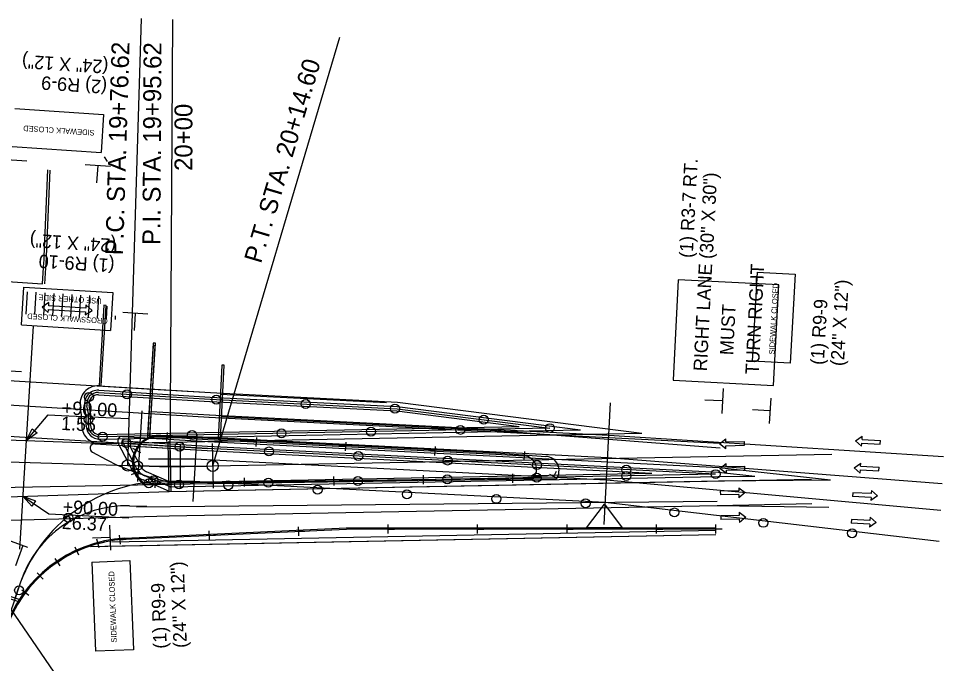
# Model space of a CAD drawing. Extents: x 659657 to 668193, y 633084 to 648639.
# Drawn here: x 662767.5 to 663181.2, y 642314.3 to 642602.8 of the extents above; entities that cross this region are included whole.
import ezdxf

# ---------------------------------------------------------------- set-up
doc = ezdxf.new("R2010")
doc.units = 0
for name, color, linetype in [('R_Border PE', 7, 'Continuous'), ('R_Draft', 7, 'Continuous'), ('R_MOT_Stage 1C_Striping', 7, 'Continuous'), ('R_MOT_Stage 2', 7, 'Continuous'), ('R_MOT_Stage 2_Striping', 7, 'Continuous'), ('R_MOT_Stage 3', 7, 'Continuous'), ('R_MOT_Stage 3_Striping', 7, 'Continuous'), ('R_MOT_Stage 4', 7, 'Continuous'), ('R_MOT_STAGE 4_ALG', 7, 'Continuous'), ('R_MOT_Stage 4_Striping', 7, 'Continuous'), ('R_MOT_Stage 5', 7, 'Continuous'), ('R_MOT_Stage 5_Striping', 7, 'Continuous'), ('R_MOT_Stage 5_Striping_PPM', 7, 'Continuous'), ('R_ROW Annot', 7, 'Continuous'), ('STRIPE-WHITE 12in', 7, 'Continuous'), ('T_Notes', 7, 'Continuous'), ('T_SIGNAL CONTROL CABINET', 7, 'Continuous'), ('TEXT_TEMP_SIGNAL_POLES_STAGE 2', 7, 'Continuous')]:
    doc.layers.add(name, color=color, linetype=linetype)

msp = doc.modelspace()

# ---------------------------------------------------------------- linework, layer by layer
for p, q in [((662739.64, 642446.41), (662768.94, 642444.98)), ((662786.79, 642425.28), (662816.56, 642423.84)), ((662713.96, 642406.03), (662816.41, 642402.89)), ((662787.14, 642380.99), (662816.91, 642379.54))]:
    msp.add_line(p, q)
for points in [[(662770.98, 642413.89), (662780.8, 642425.58), (662786.79, 642425.28)], [(662769.48, 642389.1), (662781.14, 642381.28), (662787.14, 642380.99)]]:
    msp.add_lwpolyline(points)
for points in [[(662770.98, 642413.89), (662773.61, 642419.28), (662775.84, 642417.41)], [(662769.48, 642389.1), (662775.13, 642387.07), (662773.51, 642384.65)]]:
    msp.add_lwpolyline(points, close=True)
msp.add_arc((662839.74, 643164.53), 762, 268.24549, 271.10143)
at = {"layer": 'R_Border PE'}
for p, q in [((662808.29, 642376.24), (662808.71, 642365)), ((662808.34, 642370.64), (662800.66, 642370.35)), ((662800.41, 642359.68), (662817.4, 642360.32)), ((662800.41, 642359.68), (662801.91, 642319.85)), ((662817.4, 642360.32), (662818.9, 642320.49)), ((662818.9, 642320.49), (662801.91, 642319.85))]:
    msp.add_line(p, q, dxfattribs=at)
at = {"layer": 'R_Draft'}
for p, q in [((662768.85, 642465.72), (662769.91, 642482.69)), ((662769.91, 642482.69), (662809.7, 642480.2)), ((662809.7, 642480.2), (662808.63, 642463.23)), ((662814.16, 642471.4), (662825.38, 642470.7)), ((662819.73, 642470.89), (662819.25, 642463.23)), ((662768.85, 642465.72), (662808.63, 642463.23))]:
    msp.add_line(p, q, dxfattribs=at)
for points in [[(662800.45, 642472.26), (662797.67, 642474.69), (662797.59, 642473.29), (662781.07, 642474.32), (662781.15, 642475.72), (662778.1, 642473.66), (662780.87, 642471.23), (662780.96, 642472.64), (662797.48, 642471.6), (662797.39, 642470.2)], [(663029.53, 642385.61), (663037.49, 642375), (663021.58, 642375)]]:
    msp.add_lwpolyline(points, close=True, dxfattribs=at)
at = {"layer": 'R_MOT_Stage 1C_Striping'}
for p, q in [((662817.25, 642384.85), (662824.86, 642384.64)), ((662768.45, 642350.7), (662761.02, 642328.43))]:
    msp.add_line(p, q, dxfattribs=at)
msp.add_arc((662815.88, 642334.87), 50, 88.4238, 161.5452, dxfattribs=at)
at = {"layer": 'R_MOT_Stage 2'}
for centre in [(662825.82, 642394.87), (662861.33, 642394.05), (662901.28, 642392.02), (662941.23, 642389.99), (662981.18, 642387.96), (663021.12, 642385.93), (663060.84, 642381.87), (662789.8, 642379.51), (663100.57, 642377.22), (663140.3, 642372.58), (662767.83, 642347.07)]:
    msp.add_circle(centre, 2, dxfattribs=at)
at = {"layer": 'R_MOT_Stage 2_Striping'}
for p, q in [((662826.92, 642427.09), (662852.91, 642425.52)), ((662852.76, 642425.52), (663031.46, 642416.45)), ((662826.23, 642415.85), (662847.24, 642415.84)), ((662847.24, 642415.84), (662852.3, 642415.53)), ((662852.3, 642415.53), (663030.95, 642406.46)), ((663031.46, 642416.45), (663181.16, 642406.84)), ((662825.61, 642405.87), (662846.63, 642405.86)), ((662846.63, 642405.86), (662851.7, 642405.55)), ((662851.7, 642405.55), (663030.44, 642396.47)), ((663030.95, 642406.46), (663180.55, 642394.85)), ((663030.44, 642396.47), (663179.94, 642382.87)), ((662833.88, 642395.88), (662846.03, 642395.9)), ((662846.03, 642395.9), (662851.1, 642395.57)), ((662851.1, 642395.57), (663029.94, 642386.49)), ((663029.94, 642386.49), (663179.24, 642369.03)), ((662766.07, 642343.57), (662767.56, 642348.04))]:
    msp.add_line(p, q, dxfattribs=at)
msp.add_lwpolyline([(662826.26, 642416.35), (662828.81, 642457.56), (662827.78, 642457.62), (662825.23, 642416.41)], close=True, dxfattribs=at)
msp.add_arc((662833.96, 642325.88), 70, 90.0685, 161.5452, dxfattribs=at)
at = {"layer": 'R_MOT_Stage 3'}
for p, q in [((662813.92, 642413.84), (662852.06, 642411.54)), ((662820.13, 642401.91), (662813.92, 642413.84)), ((662821.91, 642402.84), (662817.33, 642411.64)), ((662817.33, 642411.64), (662851.94, 642409.55)), ((662851.96, 642409.55), (663050.7, 642399.45)), ((662852.06, 642411.54), (663080.62, 642399.93)), ((662835.82, 642395.32), (662824.83, 642400.11)), ((662835.42, 642393.31), (662824.03, 642398.27)), ((662835.42, 642393.31), (663080.46, 642398.02)), ((662835.82, 642395.32), (663050.7, 642399.45)), ((663080.47, 642398.02), (663096.73, 642398.14)), ((663080.56, 642399.94), (663096.73, 642398.14)), ((662799.76, 642366.62), (663079.4, 642372))]:
    msp.add_line(p, q, dxfattribs=at)
for centre in [(662815.74, 642412.87), (662839.59, 642411.29), (662879.54, 642409.15), (662919.48, 642407.12), (662820.99, 642402.87), (662959.43, 642405.09), (662999.38, 642403.06), (663039.29, 642398.23), (663039.33, 642401.03), (663079.28, 642399), (662827.88, 642396.25), (662839.32, 642394.38), (662879.31, 642395.15), (662919.31, 642395.92), (662959.3, 642396.69), (662999.29, 642397.46)]:
    msp.add_circle(centre, 2, dxfattribs=at)
for radius in [8, 6]:
    msp.add_arc((662827.23, 642405.61), radius, 207.4831, 246.4596, dxfattribs=at)
at = {"layer": 'R_MOT_Stage 3_Striping'}
for p, q in [((662717.68, 642443.7), (662827.48, 642437.07)), ((662582.26, 642440.85), (662852.85, 642424.52)), ((662827.48, 642437.07), (662853.39, 642435.51)), ((662853.39, 642435.51), (662937.09, 642431.25)), ((662852.73, 642424.53), (663081.34, 642412.91)), ((662818.36, 642400.99), (662812.15, 642412.92)), ((662814.05, 642415.84), (662852.17, 642413.54)), ((662852.17, 642413.54), (663080.78, 642401.92)), ((663080.78, 642401.92), (663130.57, 642396.39)), ((662835.03, 642391.3), (662823.23, 642396.44)), ((662835.03, 642391.3), (663080.48, 642396.02)), ((663080.48, 642396.02), (663130.57, 642396.39)), ((662695.36, 642386.62), (662834.74, 642391.3)), ((662695.36, 642386.62), (662834.74, 642391.3)), ((662834.95, 642380.3), (663079.92, 642385.01)), ((663079.92, 642385.01), (663129.95, 642384.18)), ((662695.55, 642376.62), (662834.95, 642380.3)), ((662695.55, 642376.62), (662834.95, 642380.3))]:
    msp.add_line(p, q, dxfattribs=at)
msp.add_lwpolyline([(662826.24, 642415.1), (662828.73, 642456.35), (662827.7, 642456.41), (662825.21, 642415.17)], close=True, dxfattribs=at)
for centre, radius, start, end in [((662813.92, 642413.84), 2, 86.5452, 207.4831), ((662827.23, 642405.61), 10, 207.4831, 246.4596)]:
    msp.add_arc(centre, radius, start, end, dxfattribs=at)
at = {"layer": 'R_MOT_Stage 4'}
for p, q in [((662803.31, 642434.52), (662853.15, 642431.51)), ((662803.43, 642436.52), (662853.27, 642433.51)), ((662853.29, 642433.51), (662936.91, 642429.26)), ((662853.19, 642431.51), (662936.73, 642427.27)), ((662936.91, 642429.26), (663018.86, 642418.84)), ((662936.73, 642427.27), (662991.42, 642420.31)), ((662803.89, 642416.71), (662991.42, 642420.31)), ((662803.93, 642414.71), (663018.86, 642418.84)), ((662806.18, 642366.74), (663079.4, 642372))]:
    msp.add_line(p, q, dxfattribs=at)
for points in [[(662797.81, 642420.79), (662797.83, 642421.79), (662797.77, 642423.76), (662797.64, 642425.72), (662797.43, 642427.68), (662797.18, 642429.4)], [(662799.8, 642426.32), (662799.14, 642429.78)], [(662799.81, 642420.76), (662799.88, 642425.52)]]:
    msp.add_lwpolyline(points, dxfattribs=at)
for centre in [(662799.03, 642433.47), (662816.08, 642434.75), (662856.01, 642432.37), (662895.96, 642430.34), (662935.9, 642428.31), (662798.85, 642423.47), (662975.59, 642423.33), (662965.15, 642418.81), (663005.14, 642419.58), (662805.18, 642415.73), (662845.17, 642416.5), (662885.16, 642417.27), (662925.15, 642418.04)]:
    msp.add_circle(centre, 2, dxfattribs=at)
for centre, radius, start, end in [((662803.07, 642430.53), 6, 86.5452, 190.8515), ((662803.07, 642430.53), 4, 86.5452, 190.8515), ((662795.88, 642425.57), 4, 359.2337, 10.8515), ((662803.81, 642420.71), 6, 179.2337, 271.1014), ((662803.81, 642420.71), 4, 179.2337, 271.1014)]:
    msp.add_arc(centre, radius, start, end, dxfattribs=at)
at = {"layer": 'R_MOT_STAGE 4_ALG'}
for p, q in [((662713.96, 642406.03), (662816.41, 642402.89)), ((662816.41, 642402.89), (662835.4, 642402.31)), ((662835.4, 642402.31), (662854.39, 642402.68))]:
    msp.add_line(p, q, dxfattribs=at)
for points in [[(662816.41, 642402.89), (662822.54, 642602.8)], [(662835.4, 642402.31), (662836.54, 642602.31)], [(662854.39, 642402.68), (662911.29, 642594.41)], [(662839.78, 642412.53), (662839.78, 642392.53)], [(662854.2, 642412.67), (662854.58, 642392.68)], [(662854.2, 642412.67), (662854.58, 642392.68)]]:
    msp.add_lwpolyline(points, dxfattribs=at)
for centre in [(662816.41, 642402.89), (662854.39, 642402.68)]:
    msp.add_circle(centre, 2.5, dxfattribs=at)
msp.add_arc((662839.74, 643164.53), 762, 268.24549, 271.10143, dxfattribs=at)
at = {"layer": 'R_MOT_Stage 4_Striping'}
for p, q in [((662803.55, 642438.51), (662853.39, 642435.51)), ((662853.39, 642435.51), (662937.09, 642431.25)), ((662937.09, 642431.25), (663046.3, 642417.37)), ((662803.96, 642412.71), (662688.02, 642416.85)), ((662803.96, 642412.71), (663046.3, 642417.37)), ((662713.96, 642406.03), (662816.41, 642402.89)), ((662854.39, 642402.68), (663131.19, 642408)), ((662834.74, 642391.3), (663122.12, 642396.82)), ((662696.36, 642386.65), (662834.74, 642391.3)), ((662834.95, 642380.3), (663079.92, 642385.01)), ((663079.92, 642385.01), (663122.34, 642385.82)), ((662696.55, 642376.64), (662834.95, 642380.3)), ((662809.23, 642368.8), (663079.37, 642373.99))]:
    msp.add_line(p, q, dxfattribs=at)
for points in [[(662804.58, 642438.45), (662806.81, 642474.45), (662805.78, 642474.51), (662803.55, 642438.52)], [(662835.77, 642391.32), (662835.34, 642413.31), (662834.31, 642413.29), (662834.74, 642391.3)]]:
    msp.add_lwpolyline(points, close=True, dxfattribs=at)
msp.add_lwpolyline([(662795.84, 642421.34), (662795.77, 642423.67), (662795.65, 642425.55), (662795.44, 642427.43), (662795.2, 642429.07)], dxfattribs=at)
for centre, radius, start, end in [((662803.07, 642430.53), 8, 86.5452, 190.4984), ((662803.81, 642420.71), 8, 175.4291, 271.1014), ((662839.74, 643164.53), 762, 268.24549, 271.10143)]:
    msp.add_arc(centre, radius, start, end, dxfattribs=at)
at = {"layer": 'R_MOT_Stage 5'}
for p, q in [((662834.04, 642417.62), (662833.8, 642413.65)), ((662833.86, 642415.65), (662831.15, 642415.81)), ((662873.72, 642413.42), (662871.01, 642413.58)), ((662873.9, 642415.39), (662873.66, 642411.42)), ((662913.85, 642413.36), (662913.61, 642409.39)), ((662818.5, 642410.58), (662822.03, 642408.74)), ((662820.23, 642409.61), (662818.97, 642407.21)), ((662913.67, 642411.39), (662910.96, 642411.55)), ((662953.62, 642409.36), (662950.91, 642409.52)), ((662953.8, 642411.33), (662953.56, 642407.36)), ((662993.75, 642409.14), (662993.48, 642405.17)), ((662993.56, 642407.17), (662990.85, 642407.35)), ((662818.13, 642398.86), (662821.76, 642400.47)), ((663006.88, 642397.97), (663008.09, 642400.41)), ((662819.96, 642399.61), (662821.06, 642397.13)), ((662828.67, 642392.85), (662828.61, 642396.82)), ((662868.66, 642393.42), (662868.61, 642397.4)), ((662908.66, 642393.99), (662908.6, 642397.97)), ((662908.69, 642395.97), (662911.4, 642396.01)), ((662948.66, 642394.56), (662948.6, 642398.54)), ((662948.69, 642396.54), (662951.4, 642396.58)), ((662988.65, 642395.13), (662988.59, 642399.11)), ((662988.68, 642397.11), (662991.4, 642397.15)), ((663008.63, 642397.05), (663005.07, 642398.81)), ((662828.7, 642394.83), (662831.41, 642394.86)), ((662868.69, 642395.4), (662871.41, 642395.44)), ((662892.96, 642371.46), (662892.78, 642375.43)), ((662932.85, 642372.44), (662932.84, 642376.42)), ((662972.85, 642372.46), (662972.84, 642376.44)), ((663012.85, 642372.48), (663012.84, 642376.45)), ((663052.85, 642372.49), (663052.84, 642376.47)), ((663079.37, 642372.51), (663079.36, 642376.48)), ((662813.16, 642367.72), (662812.78, 642371.68)), ((662853, 642369.62), (662852.82, 642373.59)), ((662852.97, 642371.6), (662855.68, 642371.72)), ((662892.93, 642373.44), (662895.64, 642373.56)), ((662932.9, 642374.42), (662935.62, 642374.42)), ((662972.9, 642374.44), (662975.62, 642374.44)), ((663012.9, 642374.46), (663015.62, 642374.46)), ((663052.9, 642374.47), (663055.62, 642374.47)), ((663079.42, 642374.48), (663082.14, 642374.49)), ((662803.65, 642366.01), (662802.62, 642369.86)), ((662803.2, 642367.94), (662805.82, 642368.64)), ((662813.03, 642369.7), (662815.73, 642369.96)), ((662794.56, 642362.75), (662792.91, 642366.37)), ((662793.79, 642364.58), (662796.26, 642365.7)), ((662786.14, 642358.03), (662783.91, 642361.32)), ((662785.08, 642359.7), (662787.33, 642361.22)), ((662778.62, 642351.97), (662775.87, 642354.85)), ((662777.29, 642353.44), (662779.26, 642355.32)), ((662772.2, 642344.75), (662769.02, 642347.14)), ((662770.65, 642345.98), (662772.28, 642348.16))]:
    msp.add_line(p, q, dxfattribs=at)
at = {"layer": 'R_MOT_Stage 5_Striping'}
for p, q in [((662857.82, 642434.78), (662932.07, 642431.01)), ((662858.31, 642424.74), (662981.5, 642418.48)), ((662981.5, 642418.48), (663081.23, 642410.75)), ((662831.18, 642416.31), (662852.27, 642415.04)), ((662852.23, 642415.04), (662980.99, 642408.5)), ((662981.03, 642408.49), (663003.32, 642406.94)), ((663008.04, 642396.89), (662823.94, 642394.26)), ((663080.01, 642386.76), (662820.28, 642384.22)), ((662815.13, 642370.37), (662914.13, 642374.92)), ((662914.13, 642374.92), (663079.36, 642374.99))]:
    msp.add_line(p, q, dxfattribs=at)
msp.add_lwpolyline([(662858.48, 642447.76), (662856.81, 642414.81), (662857.81, 642414.75), (662859.48, 642447.71)], close=True, dxfattribs=at)
for centre, radius, start, end in [((662830.46, 642404.33), 12, 86.5452, 237.0823), ((663002.93, 642400.63), 6.33, 323.8242, 86.4599), ((662818.64, 642309.97), 60.5, 93.3216, 162.2589)]:
    msp.add_arc(centre, radius, start, end, dxfattribs=at)
at = {"layer": 'R_MOT_Stage 5_Striping_PPM'}
for p, q in [((662779.07, 642496.4), (662780.69, 642535.05)), ((662780.07, 642496.36), (662781.69, 642535.01)), ((662778.27, 642484.17), (662778.93, 642493.78)), ((662779.27, 642484.11), (662779.93, 642493.72)), ((662755.38, 642485.56), (662778.27, 642484.17)), ((662770.93, 642470.59), (662771.53, 642480.57)), ((662774.92, 642470.35), (662775.52, 642480.33)), ((662778.91, 642470.11), (662779.52, 642480.09)), ((662782.91, 642469.87), (662783.51, 642479.85)), ((662786.9, 642469.63), (662787.5, 642479.61)), ((662790.89, 642469.39), (662791.49, 642479.37)), ((662794.88, 642469.14), (662795.49, 642479.13)), ((662798.88, 642468.9), (662799.48, 642478.88)), ((662802.87, 642468.66), (662803.47, 642478.64)), ((662806.86, 642468.42), (662807.21, 642474.15)), ((662810.85, 642468.18), (662810.95, 642469.81))]:
    msp.add_line(p, q, dxfattribs=at)
msp.add_lwpolyline([(662731.6, 642354.02), (662767.54, 642342.03), (662767.86, 642342.98), (662731.92, 642354.97)], close=True, dxfattribs=at)
for radius in [99.5, 100.5]:
    msp.add_arc((662679.66, 642500.56), radius, 356.0952, 357.6052, dxfattribs=at)
at = {"layer": 'R_ROW Annot'}
for p, q in [((663082.58, 642437.34), (663082.01, 642426.11)), ((663082.14, 642431.76), (663074.47, 642432.15))]:
    msp.add_line(p, q, dxfattribs=at)
msp.add_lwpolyline([(663062.52, 642485.93), (663060.24, 642440.98), (663105.18, 642438.7), (663107.46, 642483.64)], close=True, dxfattribs=at)
at = {"layer": 'STRIPE-WHITE 12in'}
for p, q in [((662755.38, 642485.56), (662778.27, 642484.17)), ((662770.93, 642470.59), (662771.53, 642480.57)), ((662774.92, 642470.35), (662775.52, 642480.33)), ((662778.91, 642470.11), (662779.52, 642480.09)), ((662782.91, 642469.87), (662783.51, 642479.85)), ((662786.9, 642469.63), (662787.5, 642479.61)), ((662790.89, 642469.39), (662791.49, 642479.37)), ((662794.88, 642469.14), (662795.49, 642479.13)), ((662798.88, 642468.9), (662799.48, 642478.88)), ((662802.87, 642468.66), (662803.47, 642478.64)), ((662806.86, 642468.42), (662807.21, 642474.15)), ((662810.85, 642468.18), (662810.95, 642469.81))]:
    msp.add_line(p, q, dxfattribs=at)
at = {"layer": 'T_Notes'}
for p, q in [((662765.84, 642562.5), (662805.62, 642559.9)), ((662805.62, 642559.9), (662804.51, 642542.93)), ((662764.74, 642545.53), (662804.51, 642542.93)), ((662805.91, 642540.86), (662807.25, 642538.86)), ((662759.99, 642539.88), (662771.21, 642539.15)), ((662797.42, 642537.52), (662808.65, 642536.78)), ((662803, 642536.99), (662802.5, 642529.33)), ((663097.91, 642489.36), (663095.67, 642449.56)), ((663097.91, 642489.36), (663114.88, 642488.41)), ((663114.88, 642488.41), (663112.65, 642448.61)), ((663112.65, 642448.61), (663095.67, 642449.56)), ((663103.89, 642432.96), (663103.26, 642421.73)), ((663103.41, 642427.39), (663095.75, 642427.82))]:
    msp.add_line(p, q, dxfattribs=at)
at = {"layer": 'T_SIGNAL CONTROL CABINET'}
for p, q in [((662774.09, 642465.34), (662768.06, 642365.52)), ((662803.37, 642435.52), (662853.21, 642432.51)), ((662852, 642410.54), (662532, 642429.86)), ((662853.24, 642432.51), (662936.82, 642428.26)), ((663029.43, 642376.54), (663032.19, 642430.95)), ((662936.82, 642428.26), (663005.14, 642419.58)), ((663005.14, 642419.58), (662803.91, 642415.71)), ((662801.7, 642412.58), (662851.95, 642409.55)), ((662801.76, 642413.58), (662852.01, 642410.54)), ((662831.15, 642415.81), (662852.24, 642414.54)), ((662852.2, 642414.54), (662980.98, 642408)), ((663080.94, 642412.53), (663083.81, 642414.84)), ((663083.9, 642410.34), (663080.94, 642412.53)), ((663083.84, 642413.43), (663083.81, 642414.84)), ((663083.84, 642413.43), (663092.12, 642413.59)), ((663092.15, 642411.9), (663092.12, 642413.59)), ((663141.76, 642413.85), (663144.79, 642415.95)), ((663144.56, 642411.45), (663141.76, 642413.85)), ((663144.56, 642411.45), (663144.63, 642412.86)), ((663144.63, 642412.86), (663152.9, 642412.44)), ((663144.72, 642414.54), (663144.79, 642415.95)), ((663144.72, 642414.54), (663152.98, 642414.12)), ((663152.9, 642412.44), (663152.98, 642414.12)), ((662851.95, 642409.55), (663050.7, 642399.45)), ((663079.28, 642399), (662852, 642410.54)), ((663083.87, 642411.74), (663092.15, 642411.9)), ((663083.9, 642410.34), (663083.87, 642411.74)), ((662980.98, 642408), (662993.6, 642407.17)), ((663081.15, 642401.53), (663084.03, 642403.84)), ((663084.11, 642399.34), (663081.15, 642401.53)), ((663084.05, 642402.43), (663084.03, 642403.84)), ((663084.05, 642402.43), (663092.33, 642402.59)), ((663084.09, 642400.75), (663092.36, 642400.91)), ((663084.11, 642399.34), (663084.09, 642400.75)), ((663092.36, 642400.91), (663092.33, 642402.59)), ((663141.15, 642401.86), (663144.18, 642403.96)), ((663143.95, 642399.47), (663141.15, 642401.86)), ((663143.95, 642399.47), (663144.03, 642400.87)), ((663144.03, 642400.87), (663152.29, 642400.45)), ((663144.11, 642402.56), (663144.18, 642403.96)), ((663144.11, 642402.56), (663152.38, 642402.14)), ((663152.29, 642400.45), (663152.38, 642402.14)), ((663079.28, 642399), (662579.98, 642389.4)), ((662997.73, 642397.24), (662824.08, 642394.76)), ((662835.48, 642395.31), (663050.7, 642399.45)), ((663089.59, 642392.94), (663089.62, 642391.54)), ((663089.59, 642392.94), (663092.55, 642390.75)), ((663089.62, 642391.54), (663081.34, 642391.38)), ((663081.34, 642391.38), (663081.38, 642389.69)), ((663089.65, 642389.85), (663081.38, 642389.69)), ((663089.65, 642389.85), (663089.68, 642388.45)), ((663092.55, 642390.75), (663089.68, 642388.45)), ((663140.59, 642390.72), (663140.5, 642389.03)), ((663148.76, 642388.61), (663140.5, 642389.03)), ((663148.85, 642390.3), (663140.59, 642390.72)), ((663151.72, 642389.31), (663148.69, 642387.21)), ((663148.76, 642388.61), (663148.69, 642387.21)), ((663148.92, 642391.7), (663148.85, 642390.3)), ((663148.92, 642391.7), (663151.72, 642389.31)), ((663089.83, 642380.54), (663081.56, 642380.38)), ((663081.56, 642380.38), (663081.59, 642378.69)), ((663089.8, 642381.95), (663089.83, 642380.54)), ((663089.8, 642381.95), (663092.77, 642379.75)), ((663092.77, 642379.75), (663089.89, 642377.45)), ((663148.31, 642379.72), (663148.24, 642378.32)), ((663148.31, 642379.72), (663151.12, 642377.32)), ((663089.86, 642378.85), (663081.59, 642378.69)), ((663089.86, 642378.85), (663089.89, 642377.45)), ((663139.98, 642378.74), (663139.89, 642377.05)), ((663148.16, 642376.63), (663139.89, 642377.05)), ((663148.24, 642378.32), (663139.98, 642378.74)), ((663151.12, 642377.32), (663148.08, 642375.23)), ((663148.16, 642376.63), (663148.08, 642375.23)), ((662815.15, 642369.87), (662914.14, 642374.42)), ((662914.14, 642374.42), (663079.36, 642374.49))]:
    msp.add_line(p, q, dxfattribs=at)
for points in [[(662798.82, 642426.13), (662798.16, 642429.59)], [(662798.81, 642420.77), (662798.88, 642425.53)], [(662820.97, 642395.68), (662822.89, 642427.33)], [(662847.3, 642416.84), (662845.49, 642386.83)], [(662800.63, 642408.82), (662806.72, 642405.52), (662808.48, 642404.62), (662810.14, 642403.82), (662811.74, 642403.08), (662813.29, 642402.4), (662814.8, 642401.78), (662816.25, 642401.19), (662817.76, 642400.61), (662819.29, 642400.05), (662820.86, 642399.5), (662822.48, 642398.95), (662824.17, 642398.41), (662825.94, 642397.86), (662827.88, 642397.29), (662829.94, 642396.72), (662832.15, 642396.14), (662835.48, 642395.31)]]:
    msp.add_lwpolyline(points, dxfattribs=at)
for centre, radius, start, end in [((662803.07, 642430.53), 5, 86.5452, 190.8515), ((662795.88, 642425.57), 3, 359.2337, 10.8515), ((662803.81, 642420.71), 5, 179.2337, 271.1014), ((662801.58, 642410.58), 2, 86.5452, 241.5347), ((662830.46, 642404.33), 11.5, 86.5452, 236.3342), ((662993.2, 642401.18), 6, 319.009, 86.2323), ((662818.64, 642309.97), 60, 93.3216, 162.2589)]:
    msp.add_arc(centre, radius, start, end, dxfattribs=at)
at = {"layer": 'TEXT_TEMP_SIGNAL_POLES_STAGE 2'}
for p, q in [((662757.02, 642371.72), (662771.51, 642366.35)), ((662769.54, 642367.08), (662766.15, 642357.94)), ((662750.29, 642358.55), (662887.64, 642158.79))]:
    msp.add_line(p, q, dxfattribs=at)

# ---------------------------------------------------------------- texts
for s, p in [('+90.00', (662786.81, 642425.78)), ('1.55', (662786.47, 642418.79)), ('+90.00', (662787.16, 642381.49)), ('26.37', (662786.82, 642374.5))]:
    msp.add_text(s, height=6, rotation=357.2199).set_placement(p)
at = {"layer": 'R_Border PE'}
for s, height, p in [('(24" X 12")', 6, (662842.89, 642321.39)), ('SIDEWALK CLOSED', 2.5, (662811.52, 642323.72)), ('(1) R9-9', 6, (662833.89, 642321.05))]:
    msp.add_text(s, height=height, rotation=92.1655, dxfattribs=at).set_placement(p)
at = {"layer": 'R_Draft'}
for s, height, p in [('(24" X 12")', 6, (662811.39, 642504.17)), ('(1) R9-10', 6, (662810.63, 642495.17)), ('USE OTHER SIDE', 2.5, (662804.81, 642477.63)), ('CROSSWALK CLOSED', 2.5, (662807.51, 642468.69))]:
    msp.add_text(s, height=height, rotation=176.4213, dxfattribs=at).set_placement(p)
at = {"layer": 'R_MOT_STAGE 4_ALG'}
for s, rotation, p in [('P.C. STA. 19+76.62', 88.2455, (662814.29, 642496.83)), ('P.I. STA. 19+95.62', 89.6735, (662830.97, 642501.46)), ('P.T. STA. 20+14.60', 73.4702, (662875.95, 642492.9)), ('20+00', 90.003, (662845.31, 642534.62))]:
    msp.add_text(s, height=8, rotation=rotation, dxfattribs=at).set_placement(p)
at = {"layer": 'R_ROW Annot'}
for s, height, p in [('(1) R3-7 RT.', 6, (663069.02, 642495.61)), ('(30" X 30")', 6, (663078.01, 642495.15)), ('RIGHT LANE', 6.01, (663075.33, 642444.92)), ('TURN RIGHT', 6.01, (663098.52, 642443.45)), ('MUST', 6.01, (663087.12, 642452.1))]:
    msp.add_text(s, height=height, rotation=87.0917, dxfattribs=at).set_placement(p)
at = {"layer": 'T_Notes'}
for s, height, rotation, p in [('(24" X 12")', 6, 176.2631, (662807.89, 642584.08)), ('(2) R9-9', 6, 176.2631, (662807.31, 642575.1)), ('SIDEWALK CLOSED', 2.5, 176.2631, (662801.65, 642552.89)), ('SIDEWALK CLOSED', 2.5, 86.7897, (663105.61, 642452.52)), ('(24" X 12")', 6, 86.6895, (663136.61, 642447.24)), ('(1) R9-9', 6, 86.6895, (663127.63, 642447.76))]:
    msp.add_text(s, height=height, rotation=rotation, dxfattribs=at).set_placement(p)

doc.saveas('drawing.dxf')
